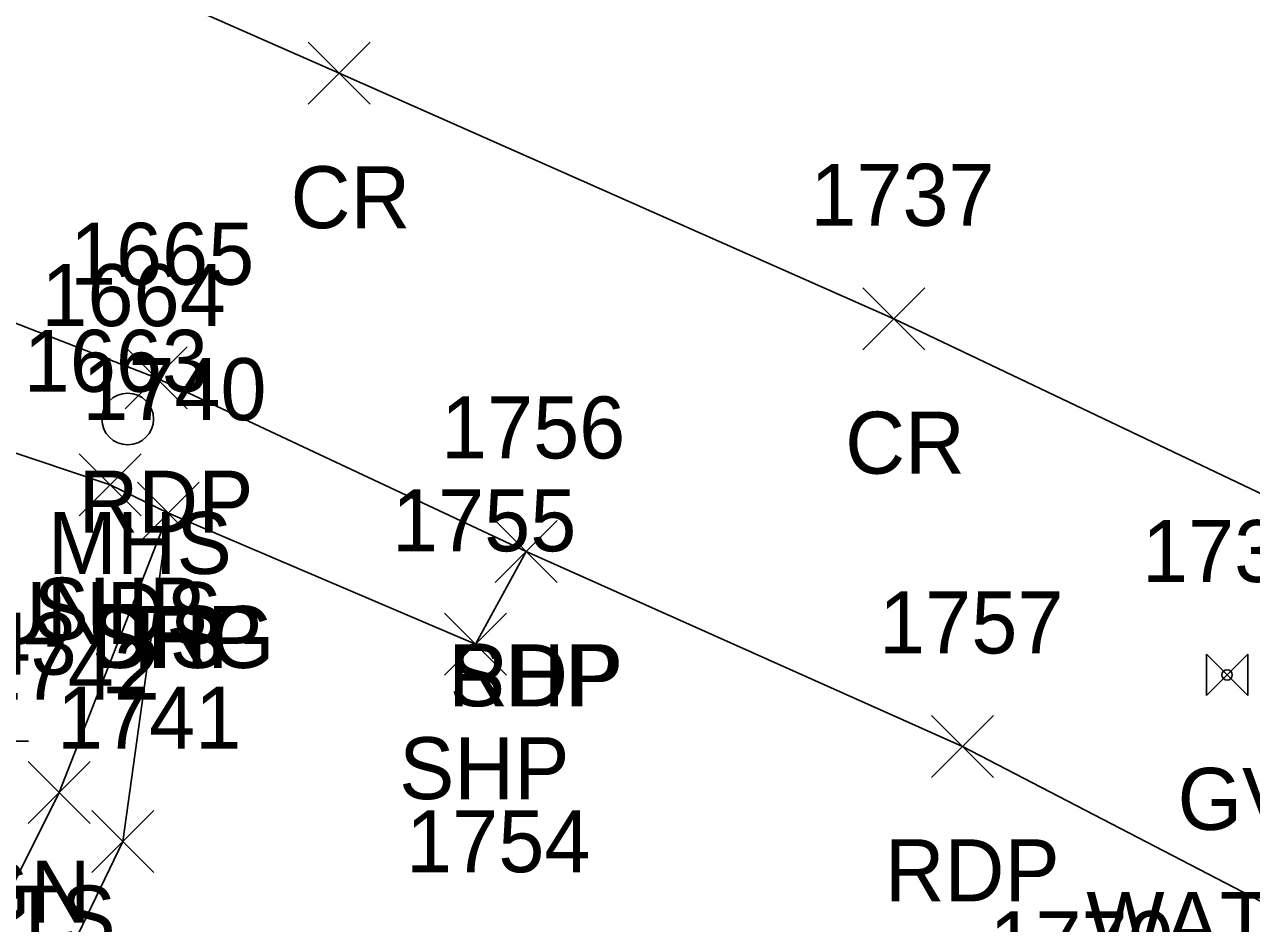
# Model space of a CAD drawing. Extents: x 1657482 to 1661439, y 647981 to 649041.
# Drawn here: x 1659908.55 to 1659948.15, y 648047.4 to 648076.41 of the extents above; entities that cross this region are included whole.
import ezdxf

# ---------------------------------------------------------------- set-up
doc = ezdxf.new("R2010")
doc.units = 0
for name, color, linetype in [('L_A', 7, 'Continuous'), ('L_I', 7, 'Continuous'), ('L_TIC', 7, 'Continuous'), ('LELB', 7, 'Continuous'), ('P_A', 7, 'Continuous'), ('P_I', 7, 'Continuous'), ('P_TIC', 7, 'Continuous'), ('PET', 7, 'Continuous'), ('PRC', 7, 'Continuous'), ('PSP', 7, 'Continuous'), ('R_A', 7, 'Continuous'), ('R_I', 7, 'Continuous'), ('R_TIC', 7, 'Continuous'), ('RDG', 7, 'Continuous'), ('S_A', 7, 'Continuous'), ('S_C', 7, 'Continuous'), ('S_I', 7, 'Continuous'), ('SSGN', 7, 'Continuous'), ('U_A', 7, 'Continuous'), ('U_C', 7, 'Continuous'), ('U_I', 7, 'Continuous'), ('USMH', 7, 'Continuous'), ('UWV', 7, 'Continuous')]:
    doc.layers.add(name, color=color, linetype=linetype)

msp = doc.modelspace()

# ---------------------------------------------------------------- linework, layer by layer
at = {"layer": 'L_TIC'}
for points in [[(1659912.188, 648059.644), (1659914.188, 648061.644)], [(1659914.188, 648059.644), (1659912.188, 648061.644)], [(1659908.66, 648050.621), (1659910.66, 648052.621)], [(1659910.66, 648050.621), (1659908.66, 648052.621)]]:
    msp.add_lwpolyline(points, dxfattribs=at)
at = {"layer": 'LELB'}
msp.add_lwpolyline([(1659913.188, 648060.644), (1659909.66, 648051.621), (1659895.052, 648022.33)], dxfattribs=at)
at = {"layer": 'P_TIC'}
for points in [[(1659917.7, 648073.839), (1659919.7, 648075.839)], [(1659919.7, 648073.839), (1659917.7, 648075.839)], [(1659935.602, 648065.916), (1659937.602, 648067.916)], [(1659937.602, 648065.916), (1659935.602, 648067.916)], [(1659911.798, 648064.014), (1659913.798, 648066.014)], [(1659913.798, 648064.014), (1659911.798, 648066.014)], [(1659910.307, 648060.558), (1659912.307, 648062.558)], [(1659912.307, 648060.558), (1659910.307, 648062.558)], [(1659912.188, 648059.644), (1659914.188, 648061.644)], [(1659914.188, 648059.644), (1659912.188, 648061.644)], [(1659923.735, 648058.408), (1659925.735, 648060.408)], [(1659925.735, 648058.408), (1659923.735, 648060.408)], [(1659923.735, 648058.408), (1659925.735, 648060.408)], [(1659925.735, 648058.408), (1659923.735, 648060.408)], [(1659922.101, 648055.41), (1659924.101, 648057.41)], [(1659924.101, 648055.41), (1659922.101, 648057.41)], [(1659937.824, 648052.114), (1659939.824, 648054.114)], [(1659939.824, 648052.114), (1659937.824, 648054.114)]]:
    msp.add_lwpolyline(points, dxfattribs=at)
at = {"layer": 'PET'}
msp.add_lwpolyline([(1659863.28, 648081.701), (1659868.598, 648080.447), (1659876.948, 648078.161), (1659883.344, 648076.024), (1659889.16, 648073.962), (1659894.185, 648071.763), (1659897.898, 648070.646), (1659905.34, 648067.906), (1659912.798, 648065.014), (1659924.735, 648059.408), (1659938.824, 648053.114), (1659959.475, 648042.397), (1659969.15, 648037.003), (1659978.866, 648031.627), (1659984.71, 648040.852), (1659990.854, 648049.845), (1659987.428, 648053.134), (1659983.709, 648058.695), (1659981.789, 648065.569), (1659981.786, 648070.317), (1659983.864, 648077.674), (1659998.695, 648097.495), (1660020.131, 648123.934)], dxfattribs=at)
at = {"layer": 'PRC'}
msp.add_lwpolyline([(1659891.684, 648086.345), (1659903.341, 648081.608), (1659918.7, 648074.839), (1659936.602, 648066.916), (1659955.342, 648057.99), (1659973.585, 648047.782), (1659984.71, 648040.852)], dxfattribs=at)
at = {"layer": 'PSP'}
msp.add_lwpolyline([(1659853.297, 648081.633), (1659859.967, 648078.251), (1659867.528, 648076.431), (1659875.609, 648074.051), (1659882.024, 648072.606), (1659887.031, 648070.628), (1659890.32, 648069.657), (1659891.23, 648070.174), (1659892.633, 648069.324), (1659893.36, 648069.756), (1659896.284, 648068.318), (1659900.161, 648067.041), (1659901.409, 648064.827), (1659902.753, 648064.423), (1659911.307, 648061.558), (1659913.188, 648060.644), (1659923.101, 648056.41), (1659924.735, 648059.408)], dxfattribs=at)
at = {"layer": 'R_TIC'}
for points in [[(1659912.188, 648059.644), (1659914.188, 648061.644)], [(1659914.188, 648059.644), (1659912.188, 648061.644)], [(1659910.716, 648049.041), (1659912.716, 648051.041)], [(1659912.716, 648049.041), (1659910.716, 648051.041)]]:
    msp.add_lwpolyline(points, dxfattribs=at)
at = {"layer": 'RDG'}
msp.add_lwpolyline([(1659913.188, 648060.644), (1659911.716, 648050.041), (1659897.454, 648020.47)], dxfattribs=at)
at = {"layer": 'SSGN'}
msp.add_line((1659905.346, 648053.282), (1659908.679, 648053.282), dxfattribs=at)
at = {"layer": 'USMH'}
for p, q in [((1659911.877, 648063.679), (1659911.877, 648063.679)), ((1659912.71, 648063.679), (1659912.71, 648063.679))]:
    msp.add_line(p, q, dxfattribs=at)
msp.add_circle((1659911.877, 648063.679), 0.833, dxfattribs=at)
at = {"layer": 'UWV'}
for p, q in [((1659946.697, 648056.086), (1659948.03, 648054.753)), ((1659948.03, 648056.086), (1659946.697, 648054.753))]:
    msp.add_line(p, q, dxfattribs=at)
for points in [[(1659946.697, 648056.086), (1659946.697, 648054.753)], [(1659948.03, 648054.753), (1659948.03, 648056.086)]]:
    msp.add_lwpolyline(points, dxfattribs=at)
msp.add_circle((1659947.363, 648055.419), 0.167, dxfattribs=at)

# ---------------------------------------------------------------- texts
at = {"layer": 'L_A'}
for p in [(1659911.597, 648055.644), (1659908.07, 648046.621)]:
    msp.add_text('TS', height=2, dxfattribs=at).set_placement(p)
at = {"layer": 'L_I'}
for s, p in [('1740', (1659910.408, 648063.644)), ('1742', (1659906.968, 648054.621)), ('1754', (1659920.863, 648049.053))]:
    msp.add_text(s, height=2, dxfattribs=at).set_placement(p)
at = {"layer": 'P_A'}
for s, p in [('CR', (1659917.134, 648069.839)), ('CR', (1659935.035, 648061.916)), ('RDP', (1659910.287, 648060.014)), ('SHP', (1659908.843, 648056.558)), ('SHP', (1659910.723, 648055.644)), ('SHP', (1659922.271, 648054.408)), ('RDP', (1659922.223, 648054.408)), ('SHP', (1659920.636, 648051.41)), ('RDP', (1659936.312, 648048.114))]:
    msp.add_text(s, height=2, dxfattribs=at).set_placement(p)
at = {"layer": 'P_I'}
for s, p in [('1737', (1659933.909, 648069.916)), ('1665', (1659910.011, 648068.014)), ('1663', (1659908.52, 648064.558)), ('1740', (1659910.408, 648063.644)), ('1756', (1659921.987, 648062.408)), ('1756', (1659921.987, 648062.408)), ('1755', (1659920.408, 648059.41)), ('1757', (1659936.131, 648056.114))]:
    msp.add_text(s, height=2, dxfattribs=at).set_placement(p)
at = {"layer": 'R_A'}
msp.add_text('DRG', height=2, dxfattribs=at).set_placement((1659910.676, 648055.644))
at = {"layer": 'R_I'}
for s, p in [('1740', (1659910.408, 648063.644)), ('1741', (1659909.591, 648053.041)), ('1770', (1659939.69, 648045.794))]:
    msp.add_text(s, height=2, dxfattribs=at).set_placement(p)
at = {"layer": 'S_A'}
msp.add_text('SIGN', height=2, dxfattribs=at).set_placement((1659904.131, 648047.429))
at = {"layer": 'S_C'}
msp.add_text('LEGAL LOAD LIMIT 24000 POUNDS', height=2, dxfattribs=at).set_placement((1659870.315, 648056.415))
at = {"layer": 'S_I'}
msp.add_text('1743', height=2, dxfattribs=at).set_placement((1659904.281, 648055.429))
at = {"layer": 'U_A'}
for s, p in [('MHS', (1659909.294, 648058.679)), ('GV', (1659945.765, 648050.419))]:
    msp.add_text(s, height=2, dxfattribs=at).set_placement(p)
at = {"layer": 'U_C'}
msp.add_text('WATER', height=2, dxfattribs=at).set_placement((1659942.82, 648046.419))
at = {"layer": 'U_I'}
for s, p in [('1664', (1659909.089, 648066.679)), ('1736', (1659944.616, 648058.419))]:
    msp.add_text(s, height=2, dxfattribs=at).set_placement(p)

doc.saveas('drawing.dxf')
